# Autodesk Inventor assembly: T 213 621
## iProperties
Created: 2005-10
Part Number: T 213 621
Document SubType Name: Assembly
Designer: I.Baliuc
Manufacturer: Standard
Standards Organization: Custom
Description: Isolator
Mass: 46.6353 g
Surface Area: 253.368 cm^2
Volume: 34.5841 cm^3
Density: 1.34846 g/cm^3
Title: Isolator
Company: Mayer & Müller AG Schaltgeräte
Zweck: für Spannungszuführung LBK
Author: T.Messerschmitt
Revision Number: 213621
Keywords: aus 213600 fertigen
